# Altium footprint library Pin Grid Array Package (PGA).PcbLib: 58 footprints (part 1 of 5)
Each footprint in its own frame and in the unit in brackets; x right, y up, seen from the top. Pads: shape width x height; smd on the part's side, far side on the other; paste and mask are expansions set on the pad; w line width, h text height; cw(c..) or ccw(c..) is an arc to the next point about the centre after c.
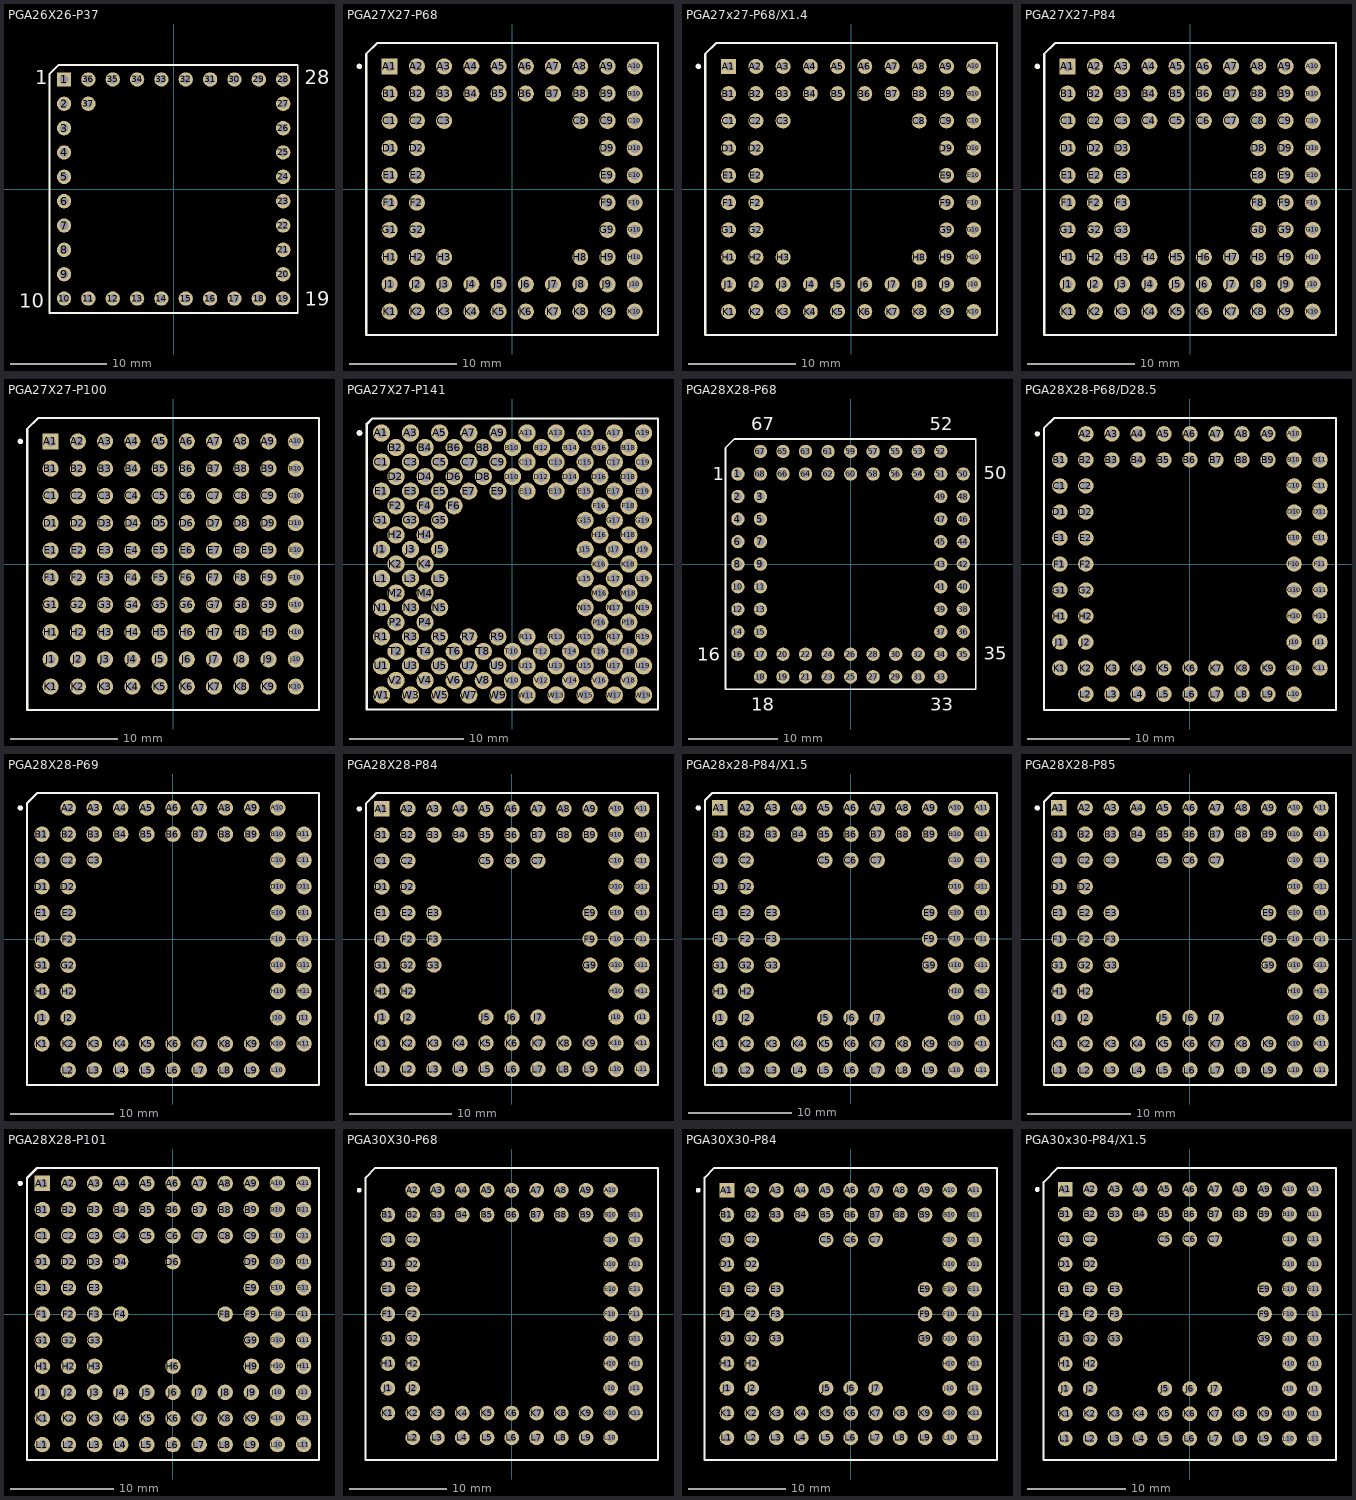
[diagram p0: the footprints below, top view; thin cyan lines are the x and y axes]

## PGA26X26-P37 [mm]
pads (37):
  rect 1.5x1.5 hole 0.9: 1(-11.43,11.43)
  round 1.5 hole 0.9: 2(-11.43,8.89) 3(-11.43,6.35) 4(-11.43,3.81) 5(-11.43,1.27) 6(-11.43,-1.27) 7(-11.43,-3.81) 8(-11.43,-6.35) 9(-11.43,-8.89) 10(-11.43,-11.43) 11(-8.89,-11.43) 12(-6.35,-11.43) 13(-3.81,-11.43) 14(-1.27,-11.43) 15(1.27,-11.43) 16(3.81,-11.43) 17(6.35,-11.43) 18(8.89,-11.43) 19(11.43,-11.43) 20(11.43,-8.89) 21(11.43,-6.35) 22(11.43,-3.81) 23(11.43,-1.27) 24(11.43,1.27) 25(11.43,3.81) 26(11.43,6.35) 27(11.43,8.89) 28(11.43,11.43) 29(8.89,11.43) 30(6.35,11.43) 31(3.81,11.43) 32(1.27,11.43) 33(-1.27,11.43) 34(-3.81,11.43) 35(-6.35,11.43) 36(-8.89,11.43) 37(-8.89,8.89)
Top Overlay:
  lines w0.2: -12.95,-12.95 -12.95,11.976 -11.976,12.95 12.95,12.95 12.95,-12.95 -12.95,-12.95
  text "1" at -14.43,10.93 h1.5
  text "28" at 13.67,10.93 h1.5
  text "19" at 13.67,-12.17 h1.5
  text "10" at -16.13,-12.37 h1.5

## PGA27X27-P68 [mm]
pads (68):
  rect 1.5x1.5 hole 0.9: A1(-11.43,11.43)
  round 1.5 hole 0.9: A2(-8.89,11.43) A3(-6.35,11.43) A4(-3.81,11.43) A5(-1.27,11.43) A6(1.27,11.43) A7(3.81,11.43) A8(6.35,11.43) A9(8.89,11.43) A10(11.43,11.43) B1(-11.43,8.89) B2(-8.89,8.89) B3(-6.35,8.89) B4(-3.81,8.89) B5(-1.27,8.89) B6(1.27,8.89) B7(3.81,8.89) B8(6.35,8.89) B9(8.89,8.89) B10(11.43,8.89) C1(-11.43,6.35) C2(-8.89,6.35) C3(-6.35,6.35) C8(6.35,6.35) C9(8.89,6.35) C10(11.43,6.35) D1(-11.43,3.81) D2(-8.89,3.81) D9(8.89,3.81) D10(11.43,3.81) E1(-11.43,1.27) E2(-8.89,1.27) E9(8.89,1.27) E10(11.43,1.27) F1(-11.43,-1.27) F2(-8.89,-1.27) F9(8.89,-1.27) F10(11.43,-1.27) G1(-11.43,-3.81) G2(-8.89,-3.81) G9(8.89,-3.81) G10(11.43,-3.81) H1(-11.43,-6.35) H2(-8.89,-6.35) H3(-6.35,-6.35) H8(6.35,-6.35) H9(8.89,-6.35) H10(11.43,-6.35) J1(-11.43,-8.89) J2(-8.89,-8.89) J3(-6.35,-8.89) J4(-3.81,-8.89) J5(-1.27,-8.89) J6(1.27,-8.89) J7(3.81,-8.89) J8(6.35,-8.89) J9(8.89,-8.89) J10(11.43,-8.89) K1(-11.43,-11.43) K2(-8.89,-11.43) K3(-6.35,-11.43) K4(-3.81,-11.43) K5(-1.27,-11.43) K6(1.27,-11.43) K7(3.81,-11.43) K8(6.35,-11.43) K9(8.89,-11.43) K10(11.43,-11.43)
Top Overlay:
  circle w0.25: c-14.25,11.43 r0.125
  lines w0.2: -13.6,-13.6 13.6,-13.6 13.6,13.6 -12.6,13.6 -13.6,12.6 -13.6,-13.6

## PGA27x27-P68/X1.4 [mm]
pads (68):
  rect 1.4x1.4 hole 0.8: A1(-11.43,11.43)
  round 1.4 hole 0.8: A2(-8.89,11.43) A3(-6.35,11.43) A4(-3.81,11.43) A5(-1.27,11.43) A6(1.27,11.43) A7(3.81,11.43) A8(6.35,11.43) A9(8.89,11.43) A10(11.43,11.43) B1(-11.43,8.89) B2(-8.89,8.89) B3(-6.35,8.89) B4(-3.81,8.89) B5(-1.27,8.89) B6(1.27,8.89) B7(3.81,8.89) B8(6.35,8.89) B9(8.89,8.89) B10(11.43,8.89) C1(-11.43,6.35) C2(-8.89,6.35) C3(-6.35,6.35) C8(6.35,6.35) C9(8.89,6.35) C10(11.43,6.35) D1(-11.43,3.81) D2(-8.89,3.81) D9(8.89,3.81) D10(11.43,3.81) E1(-11.43,1.27) E2(-8.89,1.27) E9(8.89,1.27) E10(11.43,1.27) F1(-11.43,-1.27) F2(-8.89,-1.27) F9(8.89,-1.27) F10(11.43,-1.27) G1(-11.43,-3.81) G2(-8.89,-3.81) G9(8.89,-3.81) G10(11.43,-3.81) H1(-11.43,-6.35) H2(-8.89,-6.35) H3(-6.35,-6.35) H8(6.35,-6.35) H9(8.89,-6.35) H10(11.43,-6.35) J1(-11.43,-8.89) J2(-8.89,-8.89) J3(-6.35,-8.89) J4(-3.81,-8.89) J5(-1.27,-8.89) J6(1.27,-8.89) J7(3.81,-8.89) J8(6.35,-8.89) J9(8.89,-8.89) J10(11.43,-8.89) K1(-11.43,-11.43) K2(-8.89,-11.43) K3(-6.35,-11.43) K4(-3.81,-11.43) K5(-1.27,-11.43) K6(1.27,-11.43) K7(3.81,-11.43) K8(6.35,-11.43) K9(8.89,-11.43) K10(11.43,-11.43)
Top Overlay:
  circle w0.25: c-14.25,11.43 r0.125
  lines w0.2: -13.6,-13.6 13.6,-13.6 13.6,13.6 -12.6,13.6 -13.6,12.6 -13.6,-13.6

## PGA27X27-P84 [mm]
pads (84):
  rect 1.5x1.5 hole 0.9: A1(-11.43,11.43)
  round 1.5 hole 0.9: A2(-8.89,11.43) A3(-6.35,11.43) A4(-3.81,11.43) A5(-1.27,11.43) A6(1.27,11.43) A7(3.81,11.43) A8(6.35,11.43) A9(8.89,11.43) A10(11.43,11.43) B1(-11.43,8.89) B2(-8.89,8.89) B3(-6.35,8.89) B4(-3.81,8.89) B5(-1.27,8.89) B6(1.27,8.89) B7(3.81,8.89) B8(6.35,8.89) B9(8.89,8.89) B10(11.43,8.89) C1(-11.43,6.35) C2(-8.89,6.35) C3(-6.35,6.35) C4(-3.81,6.35) C5(-1.27,6.35) C6(1.27,6.35) C7(3.81,6.35) C8(6.35,6.35) C9(8.89,6.35) C10(11.43,6.35) D1(-11.43,3.81) D2(-8.89,3.81) D3(-6.35,3.81) D8(6.35,3.81) D9(8.89,3.81) D10(11.43,3.81) E1(-11.43,1.27) E2(-8.89,1.27) E3(-6.35,1.27) E8(6.35,1.27) E9(8.89,1.27) E10(11.43,1.27) F1(-11.43,-1.27) F2(-8.89,-1.27) F3(-6.35,-1.27) F8(6.35,-1.27) F9(8.89,-1.27) F10(11.43,-1.27) G1(-11.43,-3.81) G2(-8.89,-3.81) G3(-6.35,-3.81) G8(6.35,-3.81) G9(8.89,-3.81) G10(11.43,-3.81) H1(-11.43,-6.35) H2(-8.89,-6.35) H3(-6.35,-6.35) H4(-3.81,-6.35) H5(-1.27,-6.35) H6(1.27,-6.35) H7(3.81,-6.35) H8(6.35,-6.35) H9(8.89,-6.35) H10(11.43,-6.35) J1(-11.43,-8.89) J2(-8.89,-8.89) J3(-6.35,-8.89) J4(-3.81,-8.89) J5(-1.27,-8.89) J6(1.27,-8.89) J7(3.81,-8.89) J8(6.35,-8.89) J9(8.89,-8.89) J10(11.43,-8.89) K1(-11.43,-11.43) K2(-8.89,-11.43) K3(-6.35,-11.43) K4(-3.81,-11.43) K5(-1.27,-11.43) K6(1.27,-11.43) K7(3.81,-11.43) K8(6.35,-11.43) K9(8.89,-11.43) K10(11.43,-11.43)
Top Overlay:
  circle w0.25: c-14.25,11.43 r0.125
  lines w0.2: -13.6,-13.6 -13.6,12.6 -12.6,13.6 13.6,13.6 13.6,-13.6 -13.6,-13.6

## PGA27X27-P100 [mm]
pads (100):
  rect 1.5x1.5 hole 0.9: A1(-11.43,11.43)
  round 1.5 hole 0.9: A2(-8.89,11.43) A3(-6.35,11.43) A4(-3.81,11.43) A5(-1.27,11.43) A6(1.27,11.43) A7(3.81,11.43) A8(6.35,11.43) A9(8.89,11.43) A10(11.43,11.43) B1(-11.43,8.89) B2(-8.89,8.89) B3(-6.35,8.89) B4(-3.81,8.89) B5(-1.27,8.89) B6(1.27,8.89) B7(3.81,8.89) B8(6.35,8.89) B9(8.89,8.89) B10(11.43,8.89) C1(-11.43,6.35) C2(-8.89,6.35) C3(-6.35,6.35) C4(-3.81,6.35) C5(-1.27,6.35) C6(1.27,6.35) C7(3.81,6.35) C8(6.35,6.35) C9(8.89,6.35) C10(11.43,6.35) D1(-11.43,3.81) D2(-8.89,3.81) D3(-6.35,3.81) D4(-3.81,3.81) D5(-1.27,3.81) D6(1.27,3.81) D7(3.81,3.81) D8(6.35,3.81) D9(8.89,3.81) D10(11.43,3.81) E1(-11.43,1.27) E2(-8.89,1.27) E3(-6.35,1.27) E4(-3.81,1.27) E5(-1.27,1.27) E6(1.27,1.27) E7(3.81,1.27) E8(6.35,1.27) E9(8.89,1.27) E10(11.43,1.27) F1(-11.43,-1.27) F2(-8.89,-1.27) F3(-6.35,-1.27) F4(-3.81,-1.27) F5(-1.27,-1.27) F6(1.27,-1.27) F7(3.81,-1.27) F8(6.35,-1.27) F9(8.89,-1.27) F10(11.43,-1.27) G1(-11.43,-3.81) G2(-8.89,-3.81) G3(-6.35,-3.81) G4(-3.81,-3.81) G5(-1.27,-3.81) G6(1.27,-3.81) G7(3.81,-3.81) G8(6.35,-3.81) G9(8.89,-3.81) G10(11.43,-3.81) H1(-11.43,-6.35) H2(-8.89,-6.35) H3(-6.35,-6.35) H4(-3.81,-6.35) H5(-1.27,-6.35) H6(1.27,-6.35) H7(3.81,-6.35) H8(6.35,-6.35) H9(8.89,-6.35) H10(11.43,-6.35) J1(-11.43,-8.89) J2(-8.89,-8.89) J3(-6.35,-8.89) J4(-3.81,-8.89) J5(-1.27,-8.89) J6(1.27,-8.89) J7(3.81,-8.89) J8(6.35,-8.89) J9(8.89,-8.89) J10(11.43,-8.89) K1(-11.43,-11.43) K2(-8.89,-11.43) K3(-6.35,-11.43) K4(-3.81,-11.43) K5(-1.27,-11.43) K6(1.27,-11.43) K7(3.81,-11.43) K8(6.35,-11.43) K9(8.89,-11.43) K10(11.43,-11.43)
Top Overlay:
  circle w0.25: c-14.25,11.43 r0.125
  lines w0.2: -13.6,-13.6 13.6,-13.6 13.6,13.6 -12.6,13.6 -13.6,12.6 -13.6,-13.6

## PGA27X27-P141 [mm]
pads (141):
  round 1.5 hole 0.9: A1(-11.43,11.43) A3(-8.89,11.43) A5(-6.35,11.43) A7(-3.81,11.43) A9(-1.27,11.43) A11(1.27,11.43) A13(3.81,11.43) A15(6.35,11.43) A17(8.89,11.43) A19(11.43,11.43) B2(-10.16,10.16) B4(-7.62,10.16) B6(-5.08,10.16) B8(-2.54,10.16) B10(0,10.16) B12(2.54,10.16) B14(5.08,10.16) B16(7.62,10.16) B18(10.16,10.16) C1(-11.43,8.89) C3(-8.89,8.89) C5(-6.35,8.89) C7(-3.81,8.89) C9(-1.27,8.89) C11(1.27,8.89) C13(3.81,8.89) C15(6.35,8.89) C17(8.89,8.89) C19(11.43,8.89) D2(-10.16,7.62) D4(-7.62,7.62) D6(-5.08,7.62) D8(-2.54,7.62) D10(0,7.62) D12(2.54,7.62) D14(5.08,7.62) D16(7.62,7.62) D18(10.16,7.62) E1(-11.43,6.35) E3(-8.89,6.35) E5(-6.35,6.35) E7(-3.81,6.35) E9(-1.27,6.35) E11(1.27,6.35) E13(3.81,6.35) E15(6.35,6.35) E17(8.89,6.35) E19(11.43,6.35) F2(-10.16,5.08) F4(-7.62,5.08) F6(-5.08,5.08) F16(7.62,5.08) F18(10.16,5.08) G1(-11.43,3.81) G3(-8.89,3.81) G5(-6.35,3.81) G15(6.35,3.81) G17(8.89,3.81) G19(11.43,3.81) H2(-10.16,2.54) H4(-7.62,2.54) H16(7.62,2.54) H18(10.16,2.54) J1(-11.43,1.27) J3(-8.89,1.27) J5(-6.35,1.27) J15(6.35,1.27) J17(8.89,1.27) J19(11.43,1.27) K2(-10.16,0) K4(-7.62,0) K16(7.62,0) K18(10.16,0) L1(-11.43,-1.27) L3(-8.89,-1.27) L5(-6.35,-1.27) L15(6.35,-1.27) L17(8.89,-1.27) L19(11.43,-1.27) M2(-10.16,-2.54) M4(-7.62,-2.54) M16(7.62,-2.54) M18(10.16,-2.54) N1(-11.43,-3.81) N3(-8.89,-3.81) N5(-6.35,-3.81) N15(6.35,-3.81) N17(8.89,-3.81) N19(11.43,-3.81) P2(-10.16,-5.08) P4(-7.62,-5.08) P16(7.62,-5.08) P18(10.16,-5.08) R1(-11.43,-6.35) R3(-8.89,-6.35) R5(-6.35,-6.35) R7(-3.81,-6.35) R9(-1.27,-6.35) R11(1.27,-6.35) R13(3.81,-6.35) R15(6.35,-6.35) R17(8.89,-6.35) R19(11.43,-6.35) T2(-10.16,-7.62) T4(-7.62,-7.62) T6(-5.08,-7.62) T8(-2.54,-7.62) T10(0,-7.62) T12(2.54,-7.62) T14(5.08,-7.62) T16(7.62,-7.62) T18(10.16,-7.62) U1(-11.43,-8.89) U3(-8.89,-8.89) U5(-6.35,-8.89) U7(-3.81,-8.89) U9(-1.27,-8.89) U11(1.27,-8.89) U13(3.81,-8.89) U15(6.35,-8.89) U17(8.89,-8.89) U19(11.43,-8.89) V2(-10.16,-10.16) V4(-7.62,-10.16) V6(-5.08,-10.16) V8(-2.54,-10.16) V10(0,-10.16) V12(2.54,-10.16) V14(5.08,-10.16) V16(7.62,-10.16) V18(10.16,-10.16) W1(-11.43,-11.43) W3(-8.89,-11.43) W5(-6.35,-11.43) W7(-3.81,-11.43) W9(-1.27,-11.43) W11(1.27,-11.43) W13(3.81,-11.43) W15(6.35,-11.43) W17(8.89,-11.43) W19(11.43,-11.43)
Top Overlay:
  circle w0.25: c-13.35,11.43 r0.125
  lines w0.2: -12.7,-12.7 12.7,-12.7 12.7,12.7 -12.226,12.7 -12.7,12.226 -12.7,-12.7

## PGA28X28-P68 [mm]
pads (68):
  round 1.5 hole 0.9: 1(-12.7,10.16) 2(-12.7,7.62) 3(-10.16,7.62) 4(-12.7,5.08) 5(-10.16,5.08) 6(-12.7,2.54) 7(-10.16,2.54) 8(-12.7,0) 9(-10.16,0) 10(-12.7,-2.54) 11(-10.16,-2.54) 12(-12.7,-5.08) 13(-10.16,-5.08) 14(-12.7,-7.62) 15(-10.16,-7.62) 16(-12.7,-10.16) 17(-10.16,-10.16) 18(-10.16,-12.7) 19(-7.62,-12.7) 20(-7.62,-10.16) 21(-5.08,-12.7) 22(-5.08,-10.16) 23(-2.54,-12.7) 24(-2.54,-10.16) 25(0,-12.7) 26(0,-10.16) 27(2.54,-12.7) 28(2.54,-10.16) 29(5.08,-12.7) 30(5.08,-10.16) 31(7.62,-12.7) 32(7.62,-10.16) 33(10.16,-12.7) 34(10.16,-10.16) 35(12.7,-10.16) 36(12.7,-7.62) 37(10.16,-7.62) 38(12.7,-5.08) 39(10.16,-5.08) 40(12.7,-2.54) 41(10.16,-2.54) 42(12.7,0) 43(10.16,0) 44(12.7,2.54) 45(10.16,2.54) 46(12.7,5.08) 47(10.16,5.08) 48(12.7,7.62) 49(10.16,7.62) 50(12.7,10.16) 51(10.16,10.16) 52(10.16,12.7) 53(7.62,12.7) 54(7.62,10.16) 55(5.08,12.7) 56(5.08,10.16) 57(2.54,12.7) 58(2.54,10.16) 59(0,12.7) 60(0,10.16) 61(-2.54,12.7) 62(-2.54,10.16) 63(-5.08,12.7) 64(-5.08,10.16) 65(-7.62,12.7) 66(-7.62,10.16) 67(-10.16,12.7) 68(-10.16,10.16)
Top Overlay:
  lines w0.2: -14.1,-14.1 -14.1,13.1 -13.1,14.1 14.1,14.1 14.1,-14.1 -14.1,-14.1
  text "67" at -11.18,15.08 h1.5
  text "52" at 8.9,15.08 h1.5
  text "50" at 15,9.55 h1.5
  text "35" at 15,-10.77 h1.5
  text "33" at 8.96,-16.55 h1.5
  text "16" at -17.31,-10.87 h1.5
  text "1" at -15.51,9.45 h1.5
  text "18" at -11.22,-16.55 h1.5

## PGA28X28-P68/D28.5 [mm]
pads (68):
  round 1.5 hole 0.9: A2(-10.16,12.7) A3(-7.62,12.7) A4(-5.08,12.7) A5(-2.54,12.7) A6(0,12.7) A7(2.54,12.7) A8(5.08,12.7) A9(7.62,12.7) A10(10.16,12.7) B1(-12.7,10.16) B2(-10.16,10.16) B3(-7.62,10.16) B4(-5.08,10.16) B5(-2.54,10.16) B6(0,10.16) B7(2.54,10.16) B8(5.08,10.16) B9(7.62,10.16) B10(10.16,10.16) B11(12.7,10.16) C1(-12.7,7.62) C2(-10.16,7.62) C10(10.16,7.62) C11(12.7,7.62) D1(-12.7,5.08) D2(-10.16,5.08) D10(10.16,5.08) D11(12.7,5.08) E1(-12.7,2.54) E2(-10.16,2.54) E10(10.16,2.54) E11(12.7,2.54) F1(-12.7,0) F2(-10.16,0) F10(10.16,0) F11(12.7,0) G1(-12.7,-2.54) G2(-10.16,-2.54) G10(10.16,-2.54) G11(12.7,-2.54) H1(-12.7,-5.08) H2(-10.16,-5.08) H10(10.16,-5.08) H11(12.7,-5.08) J1(-12.7,-7.62) J2(-10.16,-7.62) J10(10.16,-7.62) J11(12.7,-7.62) K1(-12.7,-10.16) K2(-10.16,-10.16) K3(-7.62,-10.16) K4(-5.08,-10.16) K5(-2.54,-10.16) K6(0,-10.16) K7(2.54,-10.16) K8(5.08,-10.16) K9(7.62,-10.16) K10(10.16,-10.16) K11(12.7,-10.16) L2(-10.16,-12.7) L3(-7.62,-12.7) L4(-5.08,-12.7) L5(-2.54,-12.7) L6(0,-12.7) L7(2.54,-12.7) L8(5.08,-12.7) L9(7.62,-12.7) L10(10.16,-12.7)
Top Overlay:
  circle w0.25: c-14.9,12.7 r0.125
  lines w0.2: -14.25,-14.25 -14.25,13.25 -13.25,14.25 14.25,14.25 14.25,-14.25 -14.25,-14.25

## PGA28X28-P69 [mm]
pads (69):
  round 1.5 hole 0.9: A2(-10.16,12.7) A3(-7.62,12.7) A4(-5.08,12.7) A5(-2.54,12.7) A6(0,12.7) A7(2.54,12.7) A8(5.08,12.7) A9(7.62,12.7) A10(10.16,12.7) B1(-12.7,10.16) B2(-10.16,10.16) B3(-7.62,10.16) B4(-5.08,10.16) B5(-2.54,10.16) B6(0,10.16) B7(2.54,10.16) B8(5.08,10.16) B9(7.62,10.16) B10(10.16,10.16) B11(12.7,10.16) C1(-12.7,7.62) C2(-10.16,7.62) C3(-7.62,7.62) C10(10.16,7.62) C11(12.7,7.62) D1(-12.7,5.08) D2(-10.16,5.08) D10(10.16,5.08) D11(12.7,5.08) E1(-12.7,2.54) E2(-10.16,2.54) E10(10.16,2.54) E11(12.7,2.54) F1(-12.7,0) F2(-10.16,0) F10(10.16,0) F11(12.7,0) G1(-12.7,-2.54) G2(-10.16,-2.54) G10(10.16,-2.54) G11(12.7,-2.54) H1(-12.7,-5.08) H2(-10.16,-5.08) H10(10.16,-5.08) H11(12.7,-5.08) J1(-12.7,-7.62) J2(-10.16,-7.62) J10(10.16,-7.62) J11(12.7,-7.62) K1(-12.7,-10.16) K2(-10.16,-10.16) K3(-7.62,-10.16) K4(-5.08,-10.16) K5(-2.54,-10.16) K6(0,-10.16) K7(2.54,-10.16) K8(5.08,-10.16) K9(7.62,-10.16) K10(10.16,-10.16) K11(12.7,-10.16) L2(-10.16,-12.7) L3(-7.62,-12.7) L4(-5.08,-12.7) L5(-2.54,-12.7) L6(0,-12.7) L7(2.54,-12.7) L8(5.08,-12.7) L9(7.62,-12.7) L10(10.16,-12.7)
Top Overlay:
  circle w0.25: c-14.8,12.7 r0.125
  lines w0.2: -14.15,-14.15 -14.15,13.15 -13.15,14.15 14.15,14.15 14.15,-14.15 -14.15,-14.15

## PGA28X28-P84 [mm]
pads (84):
  rect 1.5x1.5 hole 0.9: A1(-12.7,12.7)
  round 1.5 hole 0.9: A2(-10.16,12.7) A3(-7.62,12.7) A4(-5.08,12.7) A5(-2.54,12.7) A6(0,12.7) A7(2.54,12.7) A8(5.08,12.7) A9(7.62,12.7) A10(10.16,12.7) A11(12.7,12.7) B1(-12.7,10.16) B2(-10.16,10.16) B3(-7.62,10.16) B4(-5.08,10.16) B5(-2.54,10.16) B6(0,10.16) B7(2.54,10.16) B8(5.08,10.16) B9(7.62,10.16) B10(10.16,10.16) B11(12.7,10.16) C1(-12.7,7.62) C2(-10.16,7.62) C5(-2.54,7.62) C6(0,7.62) C7(2.54,7.62) C10(10.16,7.62) C11(12.7,7.62) D1(-12.7,5.08) D2(-10.16,5.08) D10(10.16,5.08) D11(12.7,5.08) E1(-12.7,2.54) E2(-10.16,2.54) E3(-7.62,2.54) E9(7.62,2.54) E10(10.16,2.54) E11(12.7,2.54) F1(-12.7,0) F2(-10.16,0) F3(-7.62,0) F9(7.62,0) F10(10.16,0) F11(12.7,0) G1(-12.7,-2.54) G2(-10.16,-2.54) G3(-7.62,-2.54) G9(7.62,-2.54) G10(10.16,-2.54) G11(12.7,-2.54) H1(-12.7,-5.08) H2(-10.16,-5.08) H10(10.16,-5.08) H11(12.7,-5.08) J1(-12.7,-7.62) J2(-10.16,-7.62) J5(-2.54,-7.62) J6(0,-7.62) J7(2.54,-7.62) J10(10.16,-7.62) J11(12.7,-7.62) K1(-12.7,-10.16) K2(-10.16,-10.16) K3(-7.62,-10.16) K4(-5.08,-10.16) K5(-2.54,-10.16) K6(0,-10.16) K7(2.54,-10.16) K8(5.08,-10.16) K9(7.62,-10.16) K10(10.16,-10.16) K11(12.7,-10.16) L1(-12.7,-12.7) L2(-10.16,-12.7) L3(-7.62,-12.7) L4(-5.08,-12.7) L5(-2.54,-12.7) L6(0,-12.7) L7(2.54,-12.7) L8(5.08,-12.7) L9(7.62,-12.7) L10(10.16,-12.7) L11(12.7,-12.7)
Top Overlay:
  circle w0.25: c-14.9,12.7 r0.125
  lines w0.2: -14.25,-14.25 -14.25,13.216 -13.216,14.25 14.25,14.25 14.25,-14.25 -14.25,-14.25

## PGA28x28-P84/X1.5 [mm]
pads (84):
  rect 1.5x1.5 hole 0.9: A1(-12.7,12.7)
  round 1.5 hole 0.9: A2(-10.16,12.7) A3(-7.62,12.7) A4(-5.08,12.7) A5(-2.54,12.7) A6(0,12.7) A7(2.54,12.7) A8(5.08,12.7) A9(7.62,12.7) A10(10.16,12.7) A11(12.7,12.7) B1(-12.7,10.16) B2(-10.16,10.16) B3(-7.62,10.16) B4(-5.08,10.16) B5(-2.54,10.16) B6(0,10.16) B7(2.54,10.16) B8(5.08,10.16) B9(7.62,10.16) B10(10.16,10.16) B11(12.7,10.16) C1(-12.7,7.62) C2(-10.16,7.62) C5(-2.54,7.62) C6(0,7.62) C7(2.54,7.62) C10(10.16,7.62) C11(12.7,7.62) D1(-12.7,5.08) D2(-10.16,5.08) D10(10.16,5.08) D11(12.7,5.08) E1(-12.7,2.54) E2(-10.16,2.54) E3(-7.62,2.54) E9(7.62,2.54) E10(10.16,2.54) E11(12.7,2.54) F1(-12.7,0) F2(-10.16,0) F3(-7.62,0) F9(7.62,0) F10(10.16,0) F11(12.7,0) G1(-12.7,-2.54) G2(-10.16,-2.54) G3(-7.62,-2.54) G9(7.62,-2.54) G10(10.16,-2.54) G11(12.7,-2.54) H1(-12.7,-5.08) H2(-10.16,-5.08) H10(10.16,-5.08) H11(12.7,-5.08) J1(-12.7,-7.62) J2(-10.16,-7.62) J5(-2.54,-7.62) J6(0,-7.62) J7(2.54,-7.62) J10(10.16,-7.62) J11(12.7,-7.62) K1(-12.7,-10.16) K2(-10.16,-10.16) K3(-7.62,-10.16) K4(-5.08,-10.16) K5(-2.54,-10.16) K6(0,-10.16) K7(2.54,-10.16) K8(5.08,-10.16) K9(7.62,-10.16) K10(10.16,-10.16) K11(12.7,-10.16) L1(-12.7,-12.7) L2(-10.16,-12.7) L3(-7.62,-12.7) L4(-5.08,-12.7) L5(-2.54,-12.7) L6(0,-12.7) L7(2.54,-12.7) L8(5.08,-12.7) L9(7.62,-12.7) L10(10.16,-12.7) L11(12.7,-12.7)
Top Overlay:
  circle w0.25: c-14.8,12.7 r0.125
  lines w0.2: -14.15,13.4 -14.15,-14.15 14.15,-14.15 14.15,14.15 -13.4,14.15 ; -14.15,13.45 -13.45,14.15

## PGA28X28-P85 [mm]
pads (85):
  rect 1.5x1.5 hole 0.9: A1(-12.7,12.7)
  round 1.5 hole 0.9: A2(-10.16,12.7) A3(-7.62,12.7) A4(-5.08,12.7) A5(-2.54,12.7) A6(0,12.7) A7(2.54,12.7) A8(5.08,12.7) A9(7.62,12.7) A10(10.16,12.7) A11(12.7,12.7) B1(-12.7,10.16) B2(-10.16,10.16) B3(-7.62,10.16) B4(-5.08,10.16) B5(-2.54,10.16) B6(0,10.16) B7(2.54,10.16) B8(5.08,10.16) B9(7.62,10.16) B10(10.16,10.16) B11(12.7,10.16) C1(-12.7,7.62) C2(-10.16,7.62) C3(-7.62,7.62) C5(-2.54,7.62) C6(0,7.62) C7(2.54,7.62) C10(10.16,7.62) C11(12.7,7.62) D1(-12.7,5.08) D2(-10.16,5.08) D10(10.16,5.08) D11(12.7,5.08) E1(-12.7,2.54) E2(-10.16,2.54) E3(-7.62,2.54) E9(7.62,2.54) E10(10.16,2.54) E11(12.7,2.54) F1(-12.7,0) F2(-10.16,0) F3(-7.62,0) F9(7.62,0) F10(10.16,0) F11(12.7,0) G1(-12.7,-2.54) G2(-10.16,-2.54) G3(-7.62,-2.54) G9(7.62,-2.54) G10(10.16,-2.54) G11(12.7,-2.54) H1(-12.7,-5.08) H2(-10.16,-5.08) H10(10.16,-5.08) H11(12.7,-5.08) J1(-12.7,-7.62) J2(-10.16,-7.62) J5(-2.54,-7.62) J6(0,-7.62) J7(2.54,-7.62) J10(10.16,-7.62) J11(12.7,-7.62) K1(-12.7,-10.16) K2(-10.16,-10.16) K3(-7.62,-10.16) K4(-5.08,-10.16) K5(-2.54,-10.16) K6(0,-10.16) K7(2.54,-10.16) K8(5.08,-10.16) K9(7.62,-10.16) K10(10.16,-10.16) K11(12.7,-10.16) L1(-12.7,-12.7) L2(-10.16,-12.7) L3(-7.62,-12.7) L4(-5.08,-12.7) L5(-2.54,-12.7) L6(0,-12.7) L7(2.54,-12.7) L8(5.08,-12.7) L9(7.62,-12.7) L10(10.16,-12.7) L11(12.7,-12.7)
Top Overlay:
  circle w0.25: c-14.8,12.7 r0.125
  lines w0.2: -14.15,-14.15 -14.15,13.316 -13.316,14.15 14.15,14.15 14.15,-14.15 -14.15,-14.15

## PGA28X28-P101 [mm]
pads (101):
  rect 1.5x1.5 hole 0.9: A1(-12.7,12.7)
  round 1.5 hole 0.9: A2(-10.16,12.7) A3(-7.62,12.7) A4(-5.08,12.7) A5(-2.54,12.7) A6(0,12.7) A7(2.54,12.7) A8(5.08,12.7) A9(7.62,12.7) A10(10.16,12.7) A11(12.7,12.7) B1(-12.7,10.16) B2(-10.16,10.16) B3(-7.62,10.16) B4(-5.08,10.16) B5(-2.54,10.16) B6(0,10.16) B7(2.54,10.16) B8(5.08,10.16) B9(7.62,10.16) B10(10.16,10.16) B11(12.7,10.16) C1(-12.7,7.62) C2(-10.16,7.62) C3(-7.62,7.62) C4(-5.08,7.62) C5(-2.54,7.62) C6(0,7.62) C7(2.54,7.62) C8(5.08,7.62) C9(7.62,7.62) C10(10.16,7.62) C11(12.7,7.62) D1(-12.7,5.08) D2(-10.16,5.08) D3(-7.62,5.08) D4(-5.08,5.08) D6(0,5.08) D9(7.62,5.08) D10(10.16,5.08) D11(12.7,5.08) E1(-12.7,2.54) E2(-10.16,2.54) E3(-7.62,2.54) E9(7.62,2.54) E10(10.16,2.54) E11(12.7,2.54) F1(-12.7,0) F2(-10.16,0) F3(-7.62,0) F4(-5.08,0) F8(5.08,0) F9(7.62,0) F10(10.16,0) F11(12.7,0) G1(-12.7,-2.54) G2(-10.16,-2.54) G3(-7.62,-2.54) G9(7.62,-2.54) G10(10.16,-2.54) G11(12.7,-2.54) H1(-12.7,-5.08) H2(-10.16,-5.08) H3(-7.62,-5.08) H6(0,-5.08) H9(7.62,-5.08) H10(10.16,-5.08) H11(12.7,-5.08) J1(-12.7,-7.62) J2(-10.16,-7.62) J3(-7.62,-7.62) J4(-5.08,-7.62) J5(-2.54,-7.62) J6(0,-7.62) J7(2.54,-7.62) J8(5.08,-7.62) J9(7.62,-7.62) J10(10.16,-7.62) J11(12.7,-7.62) K1(-12.7,-10.16) K2(-10.16,-10.16) K3(-7.62,-10.16) K4(-5.08,-10.16) K5(-2.54,-10.16) K6(0,-10.16) K7(2.54,-10.16) K8(5.08,-10.16) K9(7.62,-10.16) K10(10.16,-10.16) K11(12.7,-10.16) L1(-12.7,-12.7) L2(-10.16,-12.7) L3(-7.62,-12.7) L4(-5.08,-12.7) L5(-2.54,-12.7) L6(0,-12.7) L7(2.54,-12.7) L8(5.08,-12.7) L9(7.62,-12.7) L10(10.16,-12.7) L11(12.7,-12.7)
Top Overlay:
  circle w0.25: c-14.85,12.7 r0.125
  lines w0.2: -14.2,-14.2 14.2,-14.2 14.2,14.2 -13.226,14.2 -14.2,13.226 -14.2,-14.2

## PGA30X30-P68 [mm]
pads (68):
  round 1.5 hole 0.9: A2(-10.16,12.7) A3(-7.62,12.7) A4(-5.08,12.7) A5(-2.54,12.7) A6(0,12.7) A7(2.54,12.7) A8(5.08,12.7) A9(7.62,12.7) A10(10.16,12.7) B1(-12.7,10.16) B2(-10.16,10.16) B3(-7.62,10.16) B4(-5.08,10.16) B5(-2.54,10.16) B6(0,10.16) B7(2.54,10.16) B8(5.08,10.16) B9(7.62,10.16) B10(10.16,10.16) B11(12.7,10.16) C1(-12.7,7.62) C2(-10.16,7.62) C10(10.16,7.62) C11(12.7,7.62) D1(-12.7,5.08) D2(-10.16,5.08) D10(10.16,5.08) D11(12.7,5.08) E1(-12.7,2.54) E2(-10.16,2.54) E10(10.16,2.54) E11(12.7,2.54) F1(-12.7,0) F2(-10.16,0) F10(10.16,0) F11(12.7,0) G1(-12.7,-2.54) G2(-10.16,-2.54) G10(10.16,-2.54) G11(12.7,-2.54) H1(-12.7,-5.08) H2(-10.16,-5.08) H10(10.16,-5.08) H11(12.7,-5.08) J1(-12.7,-7.62) J2(-10.16,-7.62) J10(10.16,-7.62) J11(12.7,-7.62) K1(-12.7,-10.16) K2(-10.16,-10.16) K3(-7.62,-10.16) K4(-5.08,-10.16) K5(-2.54,-10.16) K6(0,-10.16) K7(2.54,-10.16) K8(5.08,-10.16) K9(7.62,-10.16) K10(10.16,-10.16) K11(12.7,-10.16) L2(-10.16,-12.7) L3(-7.62,-12.7) L4(-5.08,-12.7) L5(-2.54,-12.7) L6(0,-12.7) L7(2.54,-12.7) L8(5.08,-12.7) L9(7.62,-12.7) L10(10.16,-12.7)
Top Overlay:
  circle w0.25: c-15.65,12.7 r0.125
  lines w0.2: -15,-15 -15,14 -14,15 15,15 15,-15 -15,-15

## PGA30X30-P84 [mm]
pads (84):
  rect 1.5x1.5 hole 0.9: A1(-12.7,12.7)
  round 1.5 hole 0.9: A2(-10.16,12.7) A3(-7.62,12.7) A4(-5.08,12.7) A5(-2.54,12.7) A6(0,12.7) A7(2.54,12.7) A8(5.08,12.7) A9(7.62,12.7) A10(10.16,12.7) A11(12.7,12.7) B1(-12.7,10.16) B2(-10.16,10.16) B3(-7.62,10.16) B4(-5.08,10.16) B5(-2.54,10.16) B6(0,10.16) B7(2.54,10.16) B8(5.08,10.16) B9(7.62,10.16) B10(10.16,10.16) B11(12.7,10.16) C1(-12.7,7.62) C2(-10.16,7.62) C5(-2.54,7.62) C6(0,7.62) C7(2.54,7.62) C10(10.16,7.62) C11(12.7,7.62) D1(-12.7,5.08) D2(-10.16,5.08) D10(10.16,5.08) D11(12.7,5.08) E1(-12.7,2.54) E2(-10.16,2.54) E3(-7.62,2.54) E9(7.62,2.54) E10(10.16,2.54) E11(12.7,2.54) F1(-12.7,0) F2(-10.16,0) F3(-7.62,0) F9(7.62,0) F10(10.16,0) F11(12.7,0) G1(-12.7,-2.54) G2(-10.16,-2.54) G3(-7.62,-2.54) G9(7.62,-2.54) G10(10.16,-2.54) G11(12.7,-2.54) H1(-12.7,-5.08) H2(-10.16,-5.08) H10(10.16,-5.08) H11(12.7,-5.08) J1(-12.7,-7.62) J2(-10.16,-7.62) J5(-2.54,-7.62) J6(0,-7.62) J7(2.54,-7.62) J10(10.16,-7.62) J11(12.7,-7.62) K1(-12.7,-10.16) K2(-10.16,-10.16) K3(-7.62,-10.16) K4(-5.08,-10.16) K5(-2.54,-10.16) K6(0,-10.16) K7(2.54,-10.16) K8(5.08,-10.16) K9(7.62,-10.16) K10(10.16,-10.16) K11(12.7,-10.16) L1(-12.7,-12.7) L2(-10.16,-12.7) L3(-7.62,-12.7) L4(-5.08,-12.7) L5(-2.54,-12.7) L6(0,-12.7) L7(2.54,-12.7) L8(5.08,-12.7) L9(7.62,-12.7) L10(10.16,-12.7) L11(12.7,-12.7)
Top Overlay:
  circle w0.25: c-15.65,12.7 r0.125
  lines w0.2: -15,-15 15,-15 15,15 -14,15 -15,14 -15,-15

## PGA30x30-P84/X1.5 [mm]
pads (84):
  rect 1.5x1.5 hole 0.9: A1(-12.7,12.7)
  round 1.5 hole 0.9: A2(-10.16,12.7) A3(-7.62,12.7) A4(-5.08,12.7) A5(-2.54,12.7) A6(0,12.7) A7(2.54,12.7) A8(5.08,12.7) A9(7.62,12.7) A10(10.16,12.7) A11(12.7,12.7) B1(-12.7,10.16) B2(-10.16,10.16) B3(-7.62,10.16) B4(-5.08,10.16) B5(-2.54,10.16) B6(0,10.16) B7(2.54,10.16) B8(5.08,10.16) B9(7.62,10.16) B10(10.16,10.16) B11(12.7,10.16) C1(-12.7,7.62) C2(-10.16,7.62) C5(-2.54,7.62) C6(0,7.62) C7(2.54,7.62) C10(10.16,7.62) C11(12.7,7.62) D1(-12.7,5.08) D2(-10.16,5.08) D10(10.16,5.08) D11(12.7,5.08) E1(-12.7,2.54) E2(-10.16,2.54) E3(-7.62,2.54) E9(7.62,2.54) E10(10.16,2.54) E11(12.7,2.54) F1(-12.7,0) F2(-10.16,0) F3(-7.62,0) F9(7.62,0) F10(10.16,0) F11(12.7,0) G1(-12.7,-2.54) G2(-10.16,-2.54) G3(-7.62,-2.54) G9(7.62,-2.54) G10(10.16,-2.54) G11(12.7,-2.54) H1(-12.7,-5.08) H2(-10.16,-5.08) H10(10.16,-5.08) H11(12.7,-5.08) J1(-12.7,-7.62) J2(-10.16,-7.62) J5(-2.54,-7.62) J6(0,-7.62) J7(2.54,-7.62) J10(10.16,-7.62) J11(12.7,-7.62) K1(-12.7,-10.16) K2(-10.16,-10.16) K3(-7.62,-10.16) K4(-5.08,-10.16) K5(-2.54,-10.16) K6(0,-10.16) K7(2.54,-10.16) K8(5.08,-10.16) K9(7.62,-10.16) K10(10.16,-10.16) K11(12.7,-10.16) L1(-12.7,-12.7) L2(-10.16,-12.7) L3(-7.62,-12.7) L4(-5.08,-12.7) L5(-2.54,-12.7) L6(0,-12.7) L7(2.54,-12.7) L8(5.08,-12.7) L9(7.62,-12.7) L10(10.16,-12.7) L11(12.7,-12.7)
Top Overlay:
  circle w0.25: c-15.55,12.7 r0.125
  lines w0.2: -14.9,-14.9 14.9,-14.9 14.9,14.9 -13.45,14.9 -14.9,13.45 -14.9,-14.9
